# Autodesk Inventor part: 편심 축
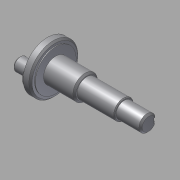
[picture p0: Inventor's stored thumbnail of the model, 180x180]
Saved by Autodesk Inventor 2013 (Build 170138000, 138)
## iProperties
Created: 2015-10
Part Number: 편심 축
Document SubType Name: Modeling
Designer: mdu
Density: 7.86 g/cm^3
Material: 강철, 연강
Mass: 86.2305 g
Surface Area: 42.7652 cm^2
Volume: 10.9708 cm^3
Author: mdu
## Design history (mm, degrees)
sketch "스케치1"
  geometry: L1 (1.75, -12.001)-(1.75, 11.999) reference; L2 (-16.95, -14)-(-16.95, 14) reference; L3 (-36.25, -18.06)-(-36.25, 18.06) reference; L4 (-41.25, 0)-(20.75, 0); L5 (-41.25, 0)-(-41.25, 15); L6 (-41.25, 15)-(-36.25, 15); L7 (-36.25, 15)-(-36.25, 7.5); L8 (-36.25, 7.5)-(-17.25, 7.5); L9 (-17.25, 6)-(5.75, 6); L10 (20.75, 5)-(20.75, 0); L11 (5.75, 6)-(5.75, 5); L12 (5.75, 5)-(20.75, 5); L13 (-17.25, -13.7)-(-17.25, 13.7) reference; L14 (-17.25, 7.5)-(-17.25, 6); 2 further points
  constraints: 20 end point, 7 perpendicular, 5 point on line, 1 collinear, 1 midpoint, 1 parallel
  dimensions: "d0" = 12 diameter of L9 L4; "d1" = 15 diameter of L8 L4; "d2" = 30 diameter of L6 L4; "d3" = 5 distance of L5.end L6.end; "d4" = 62 distance of L4.start L4.end; "d5" = 10 diameter of L12 L4; "d6" = 15 distance of L11.end L10.start
revolve "회전1" sketch "스케치1" stored, may be unused: angle "d7" = 90 deg
sketch "스케치4"
  geometry: C1 r 15 at (0, 0) reference; C2 r 12.5 at (0, 0); 1 further point
  constraints: 1 centre point, 1 coincident
  dimensions: "d24" = 25 diameter of C2
extrude "돌출4" cut sketch "스케치4" distance "d25" = 0.5; taper "d26" = 0 deg
sketch "스케치2"
  geometry: C1 r 4 at (0, -7.5); C2 r 7.5 at (0, -7.5); C3 r 15 at (0, 0) reference; 1 further point
  constraints: 2 centre point, 1 coincident, 1 tangent, 1 vertical alignment
  dimensions: "d8" = 8 diameter of C1; "d9" = 7.5 distance of point (0, 0) C1.centre
extrude "돌출1" join sketch "스케치2" distance "d10" = 10; taper "d11" = 0 deg
extrude "돌출2" join sketch "스케치2" distance "d12" = 0.5; taper "d13" = 0 deg
node "작업 평면1"
sketch "스케치3"
  geometry: L1 (-7.5, 5)-(-7.5, -5) reference; L2 (-7.5, 1.5)-(3, 1.5); L3 (3, -1.5)-(-7.5, -1.5); A1 r 1.5 centre (3, 0) between (3, -1.5) and (3, 1.5); 2 further points
  constraints: 4 end point, 2 perpendicular, 2 point on circle, 2 point on line, 2 tangent, 1 centre point, 1 horizontal alignment, 1 midpoint
  dimensions: "d14" = 3 distance between parallel lines of L3 L2; "d15" = 12 dimension on A1 L1
extrude "돌출3" cut sketch "스케치3" distance "d16" = 1.8; taper "d17" = 0 deg
chamfer "모따기1" distance "d18" = 1; stored, may be unused: second distance "d19" = 2, angle "d20" = 45 deg
chamfer "모따기2" distance "d21" = 0.5; stored, may be unused: second distance "d22" = 2, angle "d23" = 45 deg
node "솔리드1"
node "참조1"
node "참조2"
node "참조3"
node "참조4"
